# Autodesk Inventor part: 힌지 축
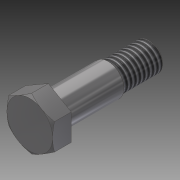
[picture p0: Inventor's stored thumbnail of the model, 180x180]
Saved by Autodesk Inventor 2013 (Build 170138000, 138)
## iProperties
Created: 2019-09
Part Number: 힌지 축
Material: 스테인리스강
Document SubType Name: Modeling
Designer: mduedu
Density: 1 g/cm^3
Author: mduedu
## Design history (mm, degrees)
sketch "스케치1"
  geometry: C1 r 4 at (0, 0); 1 further point
  constraints: 1 centre point, 1 coincident
  dimensions: "d0" = 8 diameter of C1
extrude "돌출1" new body sketch "스케치1" distance "d1" = 29; taper "d2" = 0 deg
sketch "스케치2"
  geometry: C1 r 4.5 at (0, 0); 1 further point
  constraints: 1 centre point, 1 coincident
  dimensions: "d3" = 9 diameter of C1
extrude "돌출2" join sketch "스케치2" distance "d4" = 17.5; taper "d5" = 0 deg
sketch "스케치3"
  geometry: L1 (0, 7.506)-(6.5, 3.753); L2 (6.5, 3.753)-(6.5, -3.753); L3 (6.5, -3.753)-(0, -7.506); L4 (0, -7.506)-(-6.5, -3.753); L5 (-6.5, -3.753)-(-6.5, 3.753); L6 (-6.5, 3.753)-(0, 7.506); C1 r 6.5 at (0, 0); 2 further points
  constraints: 12 end point, 2 coincident, 1 centre point, 1 tangent, 1 vertical alignment, 13 other
  dimensions: "d6" = 6.5 radius of C1
extrude "돌출3" join sketch "스케치3" distance "d8" = 5.3; taper "d9" = 0 deg
sketch "스케치4"
  geometry: L1 (-4, 11.5)-(-4.5, 11.5) reference; L2 (-4.5, 11.5)-(-4.5, 29) reference; L3 (-4.5, 29)-(-7.506, 29) reference; L4 (-7.506, 29)-(-7.506, 34.3) reference; L5 (-7.506, 34.3)-(7.506, 34.3) reference; L6 (7.506, 34.3)-(7.506, 29) reference; L7 (7.506, 29)-(4.5, 29) reference; L8 (4.5, 29)-(4.5, 11.5) reference; L9 (4.5, 11.5)-(4, 11.5) reference; L10 (4, 11.5)-(4, 0) reference; L11 (4, 0)-(-4, 0) reference; L12 (-4, 0)-(-4, 11.5) reference; L13 (0, 0)-(0, 34.3); L14 (7.506, 34.3)-(7.506, 33.746); L15 (6.506, 34.3)-(7.506, 33.746); L16 (7.506, 34.3)-(6.506, 34.3); L17 (4.5, 29)-(4, 29); L18 (4, 29)-(4, 28.5); L19 (4, 28.5)-(4.5, 28.5); L20 (4.5, 28.5)-(4.5, 29)
  constraints: 16 end point, 2 parallel, 2 perpendicular, 2 point on line, 1 horizontal, 1 midpoint
  dimensions: "d10" = 1 distance of L5.end L15.start; "d11" = 29 deg angle of L15 L5; "d12" = 0.5 distance of L19.end L7.end; "d13" = 0.5 distance of L18.end L19.end
revolve "회전1" sketch "스케치4" stored, may be unused: angle "d14" = 90 deg
feature "스레드1" dims "d15" = 10, "d16" = 0
chamfer "모따기1" distance "d17" = 0.5; stored, may be unused: second distance "d18" = 2, angle "d19" = 45 deg
chamfer "모따기2" distance "d20" = 0.5; stored, may be unused: second distance "d21" = 2, angle "d22" = 45 deg
node "솔리드1"
node "절단 모서리 투영1"
